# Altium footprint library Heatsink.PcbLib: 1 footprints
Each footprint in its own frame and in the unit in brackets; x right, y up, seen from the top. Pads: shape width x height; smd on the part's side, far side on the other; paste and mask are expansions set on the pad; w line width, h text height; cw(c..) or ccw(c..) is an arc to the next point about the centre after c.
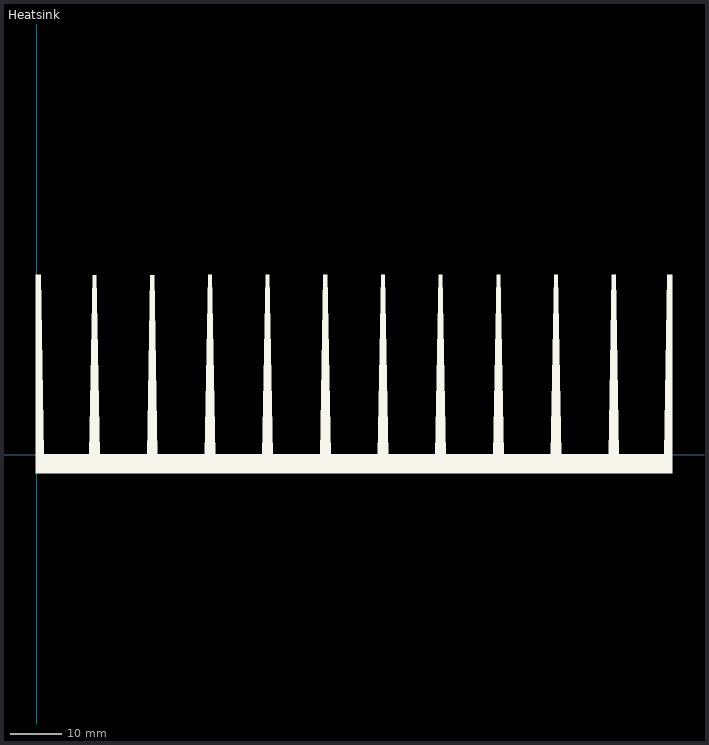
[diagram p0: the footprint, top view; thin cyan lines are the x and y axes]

## Heatsink [mm]
Top Overlay:
  region: 122.58,-0.052 123.167,35.154 124.146,35.154 124.146,-0.052
  region: 111.711,-0.052 112.374,35.154 113.08,35.154 113.743,-0.052
  region: 100.439,-0.052 101.102,35.154 101.808,35.154 102.471,-0.052
  region: 89.166,-0.052 89.829,35.152 90.535,35.152 91.198,-0.052
  region: 77.893,-0.052 78.556,35.152 79.262,35.152 79.925,-0.052
  region: 66.62,-0.052 67.284,35.152 67.989,35.152 68.652,-0.052
  region: 55.348,-0.052 56.011,35.152 56.717,35.152 57.38,-0.052
  region: 44.075,-0.052 44.738,35.148 45.444,35.148 46.107,-0.052
  region: 32.802,-0.052 33.465,35.152 34.171,35.152 34.834,-0.052
  region: 21.529,-0.052 22.193,35.143 22.898,35.143 23.561,-0.052
  region: 10.262,0 10.924,35.143 11.631,35.143 12.294,0
  region: -0.203,0 1.321,0 0.756,35.154 -0.203,35.154
  region: -0.203,0 -0.203,-3.556 124.146,-3.556 124.146,-0.052
  lines w0.254: 0,35 0,0 124,0 124,35 ; 10.333,-3.556 10.333,-3.505 ; 11.273,0 11.273,35 ; 22.545,0 22.545,35 ; 31,-3.552 31,-3.501 ; 33.818,0 33.818,35 ; 45.091,0 45.091,35 ; 51.67,-3.552 51.67,-3.501 ; 56.364,0 56.364,35 ; 67.636,0 67.636,35 ; 72.333,-3.552 72.333,-3.501 ; 78.909,0 78.909,35 ; 90.182,0 90.182,35 ; 93,-3.552 93,-3.501 ; 101.455,0 101.455,35 ; 112.727,35 112.727,0 ; 113.666,-3.552 113.666,-3.501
